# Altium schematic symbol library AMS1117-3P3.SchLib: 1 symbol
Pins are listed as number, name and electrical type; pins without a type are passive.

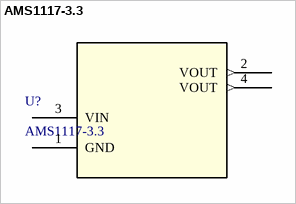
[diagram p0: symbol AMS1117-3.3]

## AMS1117-3.3
designator U?
Description; Manufacturer_Name: UMW(Youtai Semiconductor Co., Ltd.)
footprint SOT-223_UMW
pins: 1 GND (power), 2 VOUT (out), 3 VIN (power), 4 VOUT (out)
